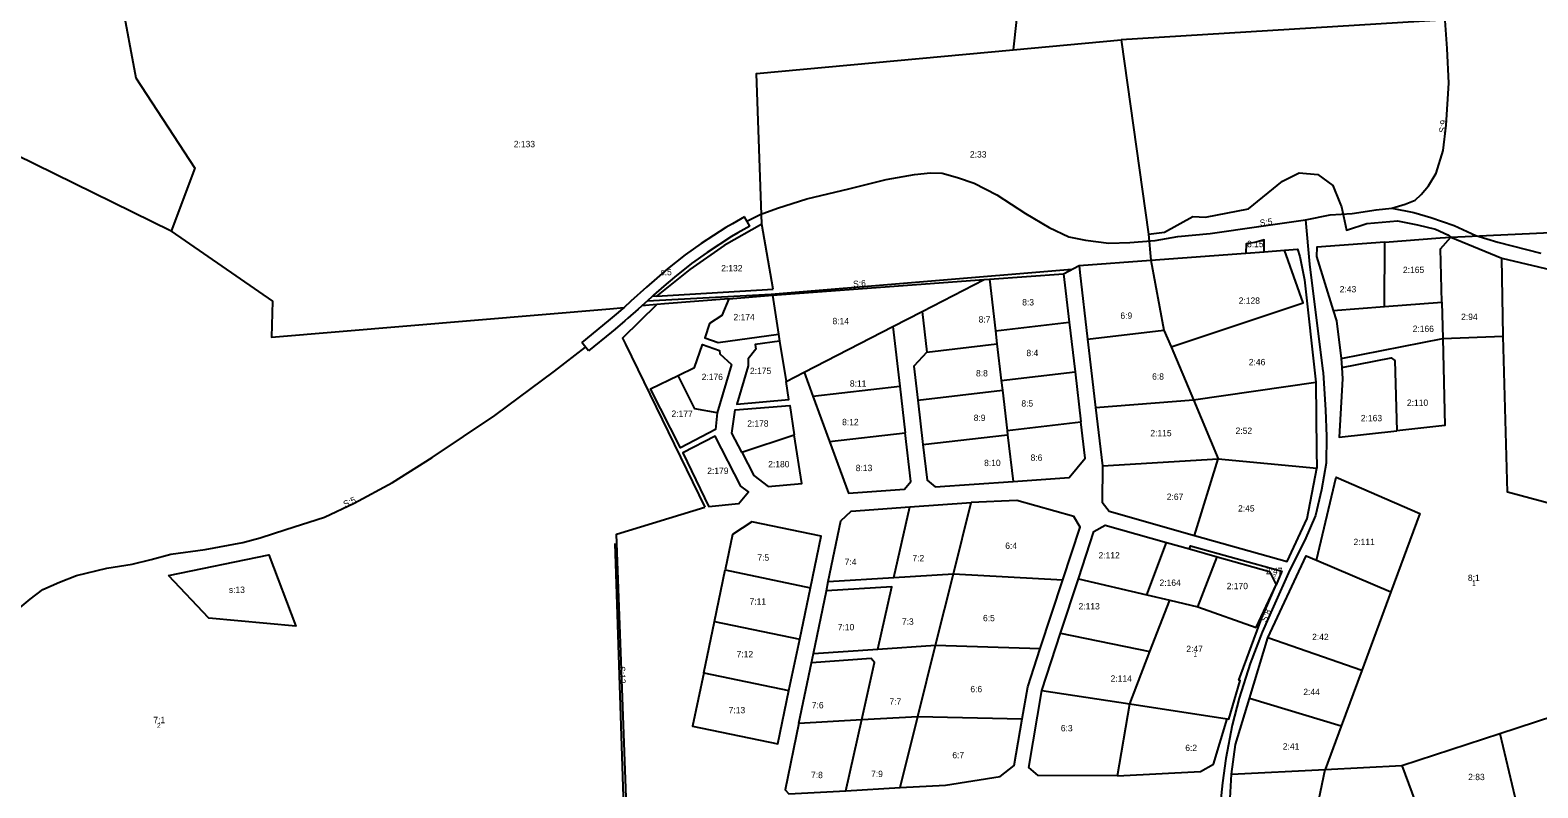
# Model space of a CAD drawing. Extents: x 140824 to 143748, y 6547319 to 6550906.
# Drawn here: x 141835 to 142666, y 6548333 to 6548751 of the extents above; entities that cross this region are included whole.
import ezdxf

# ---------------------------------------------------------------- set-up
doc = ezdxf.new("R2010")
doc.units = 0
for name, color, linetype in [('FAST Fastighetsgräns', 7, 'Continuous'), ('FAST Mittlinjeredovisad samfällighet', 7, 'Continuous'), ('FAST Områdesnummer för fastighet', 7, 'Continuous'), ('FAST Registernummer för fastighet', 7, 'Continuous'), ('FAST Registernummer för mittlinjeredovisad samfällighet', 7, 'Continuous'), ('FAST Registernummer för samfällighet', 7, 'Continuous'), ('FAST Traktgräns', 7, 'Continuous'), ('FAST Tätningsgräns för fastighetsgräns', 7, 'Continuous')]:
    doc.layers.add(name, color=color, linetype=linetype)

msp = doc.modelspace()

# ---------------------------------------------------------------- linework, layer by layer
at = {"layer": 'FAST Fastighetsgräns'}
for p, q in [((142612.62, 6548756.38), (142436.27, 6548745.52)), ((142376.67, 6548740.04), (142436.27, 6548745.52)), ((142436.27, 6548745.52), (142451.32, 6548638.42)), ((142244.43, 6548608.1), (142238.13, 6548643.9)), ((142618.17, 6548636.75), (142712.61, 6548641.27)), ((142451.32, 6548638.42), (142452.72, 6548624.05)), ((142581.59, 6548598.48), (142581.71, 6548634)), ((142618.17, 6548636.75), (142646.14, 6548625.16)), ((142413.09, 6548621.11), (142452.72, 6548624.05)), ((142452.72, 6548624.05), (142505.12, 6548627.98)), ((142452.72, 6548624.05), (142459.92, 6548585.38)), ((142505.12, 6548627.98), (142515.12, 6548628.72)), ((142515.12, 6548628.72), (142526.39, 6548629.56)), ((142646.9, 6548582.14), (142646.14, 6548625.16)), ((142363.66, 6548613.55), (142404.56, 6548616.56)), ((142404.56, 6548616.56), (142413.09, 6548621.11)), ((142404.56, 6548616.56), (142407.67, 6548589.89)), ((142180.02, 6548604.12), (142244.43, 6548608.1)), ((142244.03, 6548604.8), (142360.68, 6548613.33)), ((142326.5, 6548595.7), (142360.68, 6548613.33)), ((142360.68, 6548613.33), (142363.66, 6548613.55)), ((142363.66, 6548613.55), (142366.98, 6548585.13)), ((142180.18, 6548599.54), (142171.97, 6548598.82)), ((142180.02, 6548604.12), (142177.73, 6548604)), ((142220.04, 6548602.8), (142244.03, 6548604.8)), ((142244.03, 6548604.8), (142247.33, 6548583.3)), ((142553.22, 6548596.34), (142581.59, 6548598.48)), ((142581.59, 6548598.48), (142613.1, 6548600.85)), ((142613.1, 6548600.85), (142613.61, 6548580.87)), ((142310.4, 6548587.39), (142326.5, 6548595.7)), ((142326.5, 6548595.7), (142329.11, 6548573.37)), ((142247.33, 6548583.3), (142247.93, 6548579.37)), ((142261.52, 6548562.17), (142310.4, 6548587.39)), ((142310.4, 6548587.39), (142314.22, 6548554.61)), ((142366.98, 6548585.13), (142407.67, 6548589.89)), ((142366.98, 6548585.13), (142367.83, 6548577.88)), ((142407.67, 6548589.89), (142410.88, 6548562.36)), ((142417.82, 6548580.53), (142459.92, 6548585.38)), ((142459.92, 6548585.38), (142463.81, 6548576.19)), ((142613.61, 6548580.87), (142646.9, 6548582.14)), ((142247.93, 6548579.37), (142251.5, 6548557.04)), ((142329.11, 6548573.37), (142367.83, 6548577.88)), ((142367.83, 6548577.88), (142370.18, 6548557.62)), ((142417.82, 6548580.53), (142422.23, 6548542.71)), ((142463.81, 6548576.19), (142476.12, 6548547.08)), ((142557.57, 6548569.86), (142613.61, 6548580.87)), ((142557.57, 6548569.86), (142557.98, 6548564.85)), ((142251.5, 6548557.04), (142261.52, 6548562.17)), ((142261.52, 6548562.17), (142266.33, 6548549.02)), ((142370.18, 6548557.62), (142410.88, 6548562.36)), ((142370.18, 6548557.62), (142370.8, 6548552.29)), ((142410.88, 6548562.36), (142414.09, 6548534.85)), ((142266.33, 6548549.02), (142314.22, 6548554.61)), ((142266.33, 6548549.02), (142275.51, 6548523.93)), ((142314.22, 6548554.61), (142317.23, 6548528.78)), ((142324.14, 6548546.85), (142370.8, 6548552.29)), ((142370.8, 6548552.29), (142373.39, 6548530.11)), ((142476.12, 6548547.08), (142543.64, 6548556.8)), ((142324.14, 6548546.85), (142327.02, 6548522.28)), ((142422.23, 6548542.71), (142476.12, 6548547.08)), ((142422.23, 6548542.71), (142425.97, 6548510.6)), ((142476.12, 6548547.08), (142489.77, 6548514.39)), ((142373.39, 6548530.11), (142414.09, 6548534.85)), ((142227.15, 6548518.07), (142255.97, 6548527.63)), ((142275.51, 6548523.93), (142317.23, 6548528.78)), ((142327.02, 6548522.28), (142373.67, 6548527.71)), ((142373.39, 6548530.11), (142373.67, 6548527.71)), ((142373.67, 6548527.71), (142376.67, 6548501.95)), ((142425.97, 6548510.6), (142489.77, 6548514.39)), ((142476.77, 6548472.17), (142489.77, 6548514.39)), ((142489.77, 6548514.39), (142544.15, 6548509.25)), ((142225.38, 6548489.62), (142208.89, 6548487.99)), ((142311.01, 6548448.95), (142319.78, 6548487.89)), ((142319.78, 6548487.89), (142353.6, 6548490.29)), ((142343.81, 6548450.98), (142353.6, 6548490.29)), ((142450.39, 6548439.46), (142461.38, 6548468.26)), ((142461.38, 6548468.26), (142473.92, 6548464.73)), ((142473.92, 6548464.73), (142489.32, 6548460.39)), ((142478.62, 6548432.83), (142489.32, 6548460.39)), ((142489.32, 6548460.39), (142518.11, 6548452.24)), ((142544.04, 6548458.54), (142584.97, 6548441.06)), ((142212.02, 6548424.75), (142217.92, 6548453.14)), ((142217.92, 6548453.14), (142264.93, 6548443.36)), ((142274.83, 6548446.71), (142311.01, 6548448.95)), ((142311.01, 6548448.95), (142343.81, 6548450.98)), ((142334.01, 6548411.69), (142343.81, 6548450.98)), ((142343.81, 6548450.98), (142404.1, 6548447.75)), ((142518.11, 6548452.24), (142521.83, 6548444.93)), ((142259.03, 6548414.99), (142264.93, 6548443.36)), ((142266.61, 6548407.06), (142273.78, 6548441.64)), ((142273.78, 6548441.64), (142274.83, 6548446.71)), ((142391.68, 6548409.74), (142404.1, 6548447.75)), ((142402.89, 6548418.18), (142412.76, 6548448.29)), ((142412.76, 6548448.29), (142450.39, 6548439.46)), ((142510.67, 6548421.37), (142521.83, 6548444.93)), ((142584.97, 6548441.06), (142568.92, 6548397.7)), ((142450.39, 6548439.46), (142463.05, 6548436.49)), ((142452.16, 6548408.2), (142463.05, 6548436.49)), ((142463.05, 6548436.49), (142478.62, 6548432.83)), ((142478.62, 6548432.83), (142510.67, 6548421.37)), ((142206.11, 6548396.36), (142212.02, 6548424.75)), ((142212.02, 6548424.75), (142259.03, 6548414.99)), ((142392.57, 6548386.71), (142402.89, 6548418.18)), ((142402.89, 6548418.18), (142452.16, 6548408.2)), ((142507.05, 6548382.29), (142517.12, 6548415.77)), ((142568.92, 6548397.7), (142517.12, 6548415.77)), ((142253.13, 6548386.61), (142259.03, 6548414.99)), ((142266.61, 6548407.06), (142302.1, 6548409.5)), ((142302.1, 6548409.5), (142334.01, 6548411.69)), ((142324.19, 6548372.34), (142334.01, 6548411.69)), ((142334.01, 6548411.69), (142391.68, 6548409.74)), ((142441.09, 6548379.26), (142452.16, 6548408.2)), ((142258.62, 6548368.66), (142265.55, 6548401.97)), ((142265.55, 6548401.97), (142266.61, 6548407.06)), ((142206.11, 6548396.36), (142253.13, 6548386.61)), ((142568.92, 6548397.7), (142557.56, 6548367.02)), ((142392.57, 6548386.71), (142441.09, 6548379.26)), ((142434.25, 6548339.55), (142441.09, 6548379.26)), ((142441.09, 6548379.26), (142494.79, 6548371.02)), ((142557.56, 6548367.02), (142507.05, 6548382.29)), ((142645.15, 6548362.91), (142685.57, 6548376.24)), ((142258.62, 6548368.66), (142293.29, 6548370.64)), ((142284.43, 6548331.36), (142293.29, 6548370.64)), ((142293.29, 6548370.64), (142324.19, 6548372.34)), ((142314.4, 6548333.04), (142324.19, 6548372.34)), ((142324.19, 6548372.34), (142381.74, 6548370.99)), ((142557.56, 6548367.02), (142548.71, 6548343.09)), ((142591.08, 6548345.34), (142645.15, 6548362.91)), ((142645.15, 6548362.91), (142659.85, 6548300.41)), ((142497.13, 6548340.5), (142548.71, 6548343.09)), ((142539.85, 6548300.23), (142548.71, 6548343.09)), ((142548.71, 6548343.09), (142591.08, 6548345.34)), ((142591.08, 6548345.34), (142600.25, 6548320.44)), ((142284.43, 6548331.36), (142314.4, 6548333.04)), ((142494.77, 6548296.57), (142497.13, 6548340.5))]:
    msp.add_line(p, q, dxfattribs=at)
for points in [[(142406.77, 6549013.95), (142404.62, 6548994.39), (142376.67, 6548740.04)], [(142238.13, 6548643.9), (142235.26, 6548727.03), (142376.67, 6548740.04)], [(142451.32, 6548638.42), (142460.23, 6548639.48), (142475.91, 6548648.18), (142482.77, 6548647.83), (142506.54, 6548652.43), (142525.2, 6548667.6), (142534.41, 6548672.19), (142544.66, 6548671.32), (142552.94, 6548665.22), (142556.84, 6548655.7), (142557.78, 6548653.39), (142560.57, 6548640.61), (142571.68, 6548644.29), (142588.72, 6548645.8), (142599.66, 6548643.49), (142609.59, 6548641.21), (142616.5, 6548638.01), (142618.17, 6548636.75)], [(141912.47, 6548640.08), (141968.36, 6548601.48), (141967.78, 6548581.5), (142154.26, 6548597.18), (142162.17, 6548597.96)], [(142228.54, 6548647.93), (142222.02, 6548644.18), (142218.37, 6548642.08), (142204.68, 6548633.21), (142195.85, 6548626.92), (142186.22, 6548619.24), (142180.2, 6548614.14), (142174.55, 6548609.08), (142166, 6548601.39), (142162.17, 6548597.96)], [(142231.48, 6548642.82), (142224.97, 6548639.07), (142221.45, 6548637.04), (142207.99, 6548628.33), (142199.41, 6548622.21), (142189.97, 6548614.68), (142184.07, 6548609.7), (142178.5, 6548604.7), (142177.73, 6548604)], [(142238.13, 6548643.9), (142217.48, 6548632.15), (142198.42, 6548618.92), (142180.02, 6548604.12)], [(142515.12, 6548628.72), (142515.22, 6548635.22), (142510.09, 6548633.87), (142505.3, 6548633.08), (142505.12, 6548627.98)], [(142581.71, 6548634), (142544.11, 6548631.16), (142543.97, 6548626.07), (142553.22, 6548596.34)], [(142581.71, 6548634), (142612.18, 6548636.29), (142618.17, 6548636.75)], [(142613.1, 6548600.85), (142612.34, 6548630.31), (142618.17, 6548636.75)], [(142463.81, 6548576.19), (142536.57, 6548600.5), (142526.39, 6548629.56)], [(142526.39, 6548629.56), (142533.58, 6548630.1), (142534.73, 6548626.14), (142537.36, 6548613.25), (142543.64, 6548556.8)], [(142646.14, 6548625.16), (142703.75, 6548611.52), (142717.51, 6548603.13), (142727.33, 6548596.85), (142728.81, 6548474.79), (142649.42, 6548496.06), (142646.9, 6548582.14)], [(142413.09, 6548621.11), (142413.55, 6548617.23), (142417.82, 6548580.53)], [(142171.97, 6548598.82), (142171.73, 6548598.6), (142169.94, 6548596.99), (142164.33, 6548591.97), (142162.68, 6548590.61), (142157.3, 6548585.97), (142155.21, 6548584.26), (142142.67, 6548574.01)], [(142180.18, 6548599.54), (142161.39, 6548581.06), (142163.06, 6548577.64), (142206.82, 6548487.8)], [(142177.73, 6548604), (142175.05, 6548601.59), (142172.04, 6548598.88), (142171.97, 6548598.82)], [(142220.04, 6548602.8), (142184.47, 6548599.89), (142180.18, 6548599.54)], [(142220.04, 6548602.8), (142216.13, 6548593.45), (142209.26, 6548589.05), (142206.65, 6548581.23), (142214.14, 6548578.68), (142247.33, 6548583.3)], [(142162.17, 6548597.96), (142160.48, 6548596.44), (142158.87, 6548595.11), (142153.51, 6548590.49), (142138.94, 6548578.58)], [(142553.22, 6548596.34), (142555.03, 6548590.53), (142557.57, 6548569.86)], [(142191.95, 6548560.39), (142201.07, 6548564.81), (142205.36, 6548577.45), (142214.79, 6548574.27), (142215.05, 6548572.31), (142221.52, 6548566.52), (142213.52, 6548539.9)], [(142247.93, 6548579.37), (142234.51, 6548577.48), (142234.87, 6548574.93), (142230.63, 6548569.64), (142230.71, 6548565.71), (142224.35, 6548544.64), (142253.1, 6548547.1), (142251.5, 6548557.04)], [(142613.61, 6548580.87), (142614.75, 6548532.86), (142588.24, 6548529.96)], [(142329.11, 6548573.37), (142322.01, 6548565.52), (142324.14, 6548546.85)], [(142557.98, 6548564.85), (142585.25, 6548570.24), (142587.26, 6548568.63), (142588.24, 6548529.96)], [(142213.52, 6548539.9), (142212.68, 6548530.61), (142193.24, 6548520.49), (142176.76, 6548553.08), (142191.95, 6548560.39)], [(142213.52, 6548539.9), (142201.28, 6548542.01), (142191.95, 6548560.39)], [(142557.98, 6548564.85), (142558.4, 6548558.61), (142556.43, 6548526.48), (142588.24, 6548529.96)], [(142543.64, 6548556.8), (142544.07, 6548519.07), (142544.15, 6548509.25)], [(142227.15, 6548518.07), (142221.6, 6548528.69), (142223.44, 6548541.51), (142253.57, 6548543.93), (142255.97, 6548527.63)], [(142376.67, 6548501.95), (142407.59, 6548504.14), (142416.42, 6548514.78), (142414.09, 6548534.85)], [(142225.38, 6548489.62), (142230.81, 6548496.21), (142226.62, 6548499.3), (142212.4, 6548527.01), (142194.66, 6548517.79), (142208.89, 6548487.99)], [(142227.15, 6548518.07), (142233.81, 6548505.27), (142241.61, 6548499.26), (142260.3, 6548500.84), (142255.97, 6548527.63)], [(142275.51, 6548523.93), (142285.91, 6548495.51), (142316.83, 6548497.71), (142320.35, 6548501.96), (142317.23, 6548528.78)], [(142327.02, 6548522.28), (142329.33, 6548502.6), (142333.78, 6548498.91), (142376.67, 6548501.95)], [(142425.97, 6548510.6), (142425.84, 6548490.61), (142429.65, 6548485.49), (142476.77, 6548472.17)], [(142476.77, 6548472.17), (142527.78, 6548457.76), (142538.9, 6548481.58), (142544.15, 6548509.25)], [(142544.04, 6548458.54), (142554.87, 6548504.24), (142600.91, 6548484.22), (142584.97, 6548441.06)], [(142404.1, 6548447.75), (142413.69, 6548476.72), (142410.13, 6548482.63), (142378.7, 6548491.45), (142353.6, 6548490.29)], [(142163.49, 6548322.6), (142158.09, 6548472.86), (142206.82, 6548487.8)], [(142274.83, 6548446.71), (142281.8, 6548480.29), (142287.43, 6548485.6), (142319.78, 6548487.89)], [(142264.93, 6548443.36), (142270.83, 6548471.74), (142232.64, 6548479.68), (142222, 6548472.69), (142217.92, 6548453.14)], [(142412.76, 6548448.29), (142421.3, 6548474.34), (142427.49, 6548477.8), (142461.38, 6548468.26)], [(142473.92, 6548464.73), (142474.6, 6548466.51), (142524.92, 6548452.46), (142521.83, 6548444.93)], [(141910.98, 6548450.1), (141966.32, 6548461.52), (141981.18, 6548422.1), (141933.3, 6548426.46), (141910.98, 6548450.1)], [(142517.12, 6548415.77), (142538.38, 6548460.96), (142544.04, 6548458.54)], [(142302.1, 6548409.5), (142309.86, 6548443.86), (142273.78, 6548441.64)], [(142494.79, 6548371.02), (142495.68, 6548370.88), (142501.93, 6548392.18), (142501.19, 6548392.3), (142513.89, 6548426.73), (142521.83, 6548444.93)], [(142381.74, 6548370.99), (142384.8, 6548388.66), (142391.68, 6548409.74)], [(142293.29, 6548370.64), (142300.34, 6548402), (142298.4, 6548404.26), (142265.55, 6548401.97)], [(142206.11, 6548396.36), (142200, 6548367), (142247.03, 6548357.25), (142253.13, 6548386.61)], [(142434.25, 6548339.55), (142390.57, 6548339.72), (142385.31, 6548344.23), (142392.57, 6548386.71)], [(142497.13, 6548340.5), (142499.4, 6548356.85), (142507.05, 6548382.29)], [(142258.62, 6548368.66), (142250.96, 6548331.92), (142252.99, 6548329.6), (142284.43, 6548331.36)], [(142314.4, 6548333.04), (142339.44, 6548334.48), (142369.55, 6548339.12), (142377.29, 6548345.17), (142381.74, 6548370.99)], [(142434.25, 6548339.55), (142480.1, 6548341.97), (142487.26, 6548346.02), (142494.79, 6548371.02)]]:
    msp.add_lwpolyline(points, dxfattribs=at)
at = {"layer": 'FAST Mittlinjeredovisad samfällighet'}
msp.add_line((142157.05, 6548467.7), (142161.8, 6548322.48), dxfattribs=at)
for points in [[(142585.58, 6548652.76), (142592.83, 6548654.89), (142598.47, 6548657.22), (142601.64, 6548660.21), (142605.74, 6548665.08), (142610.04, 6548671.99), (142613.92, 6548684.49), (142615.5, 6548698.53), (142616.91, 6548721.66), (142615.99, 6548740.75), (142614.88, 6548756.3), (142614.86, 6548756.52)], [(142229.97, 6548645.59), (142237.3, 6548649.2), (142246.79, 6548652.74), (142262.93, 6548657.84), (142286.12, 6548663.48), (142306.8, 6548668.6), (142322.42, 6548671.37), (142331.25, 6548672.14), (142337.69, 6548671.96), (142345.99, 6548669.67), (142355.28, 6548666.46), (142367.71, 6548660.09), (142383.55, 6548649.81), (142396.67, 6548642.09), (142407.52, 6548636.94), (142416.71, 6548635.06), (142429.56, 6548633.37), (142441.01, 6548633.77), (142454.98, 6548634.98), (142467.51, 6548637.11), (142485.45, 6548638.79), (142512.25, 6548642.71), (142537.88, 6548646.22), (142551.6, 6548649.05), (142563.65, 6548649.87), (142576.9, 6548651.84), (142585.58, 6548652.76), (142597.69, 6548650.35), (142606.99, 6548647.59), (142619.92, 6548643.26), (142631.93, 6548637.63), (142644, 6548633.91), (142667.73, 6548627.94)], [(142537.88, 6548646.22), (142540.11, 6548621.81), (142547.32, 6548564.28), (142547.62, 6548561.9), (142548.94, 6548541.48), (142549.54, 6548526.8), (142549.27, 6548512.14), (142546.78, 6548497.25), (142543.45, 6548483.27), (142537.63, 6548469.51), (142529.38, 6548453.18), (142520.29, 6548432.91), (142514.02, 6548418.86), (142507.36, 6548401.6), (142501.38, 6548382.42), (142497.58, 6548367.57), (142493.97, 6548349.05), (142492.27, 6548335.76), (142489.65, 6548311.19)], [(142175.02, 6548601.57), (142243.22, 6548605.36), (142409.18, 6548619.06)], [(141827.07, 6548430.66), (141834.73, 6548437.04), (141841.63, 6548442.41), (141850.84, 6548446.4), (141860.34, 6548450.08), (141877.03, 6548454.15), (141891.03, 6548456.38), (141901.36, 6548458.87), (141912.3, 6548461.78), (141931.15, 6548464.46), (141951.94, 6548468.26), (141961.55, 6548470.91), (141975.76, 6548475.49), (141996.93, 6548482.35), (142013.43, 6548489.94), (142034.59, 6548501.36), (142056.41, 6548515.25), (142090.95, 6548538.3), (142123.78, 6548562.72), (142140.93, 6548576.12)]]:
    msp.add_lwpolyline(points, dxfattribs=at)
at = {"layer": 'FAST Traktgräns'}
msp.add_line((141912.47, 6548640.08), (141826.77, 6548682.21), dxfattribs=at)
msp.add_lwpolyline([(141972.63, 6548844.89), (141874.33, 6548830.86), (141877.61, 6548818.09), (141882.35, 6548808.96), (141885.06, 6548798.88), (141889.56, 6548781.75), (141885.13, 6548766.87), (141892.91, 6548724.65), (141925.47, 6548674.71), (141912.47, 6548640.08)], dxfattribs=at)
at = {"layer": 'FAST Tätningsgräns för fastighetsgräns'}
for p, q in [((142231.48, 6548642.82), (142228.54, 6548647.93)), ((142142.67, 6548574.01), (142138.94, 6548578.58))]:
    msp.add_line(p, q, dxfattribs=at)

# ---------------------------------------------------------------- texts
at = {"layer": 'FAST Områdesnummer för fastighet'}
for s, p in [('2', (142519.88, 6548448.31)), ('1', (142629.8, 6548444.55)), ('1', (142476.24, 6548405.36)), ('2', (141904.71, 6548366.11))]:
    msp.add_text(s, height=2.5, dxfattribs=at).set_placement(p)
at = {"layer": 'FAST Registernummer för fastighet'}
for s, p in [('2:133', (142101.39, 6548686.36)), ('2:33', (142352.91, 6548680.66)), ('8:15', (142505.74, 6548631.21)), ('2:132', (142215.78, 6548617.91)), ('2:165', (142591.69, 6548616.99)), ('2:43', (142556.82, 6548606.28)), ('8:3', (142381.73, 6548599.06)), ('2:128', (142501.11, 6548599.96)), ('2:174', (142222.53, 6548590.9)), ('8:14', (142277.13, 6548588.72)), ('8:7', (142357.71, 6548589.62)), ('6:9', (142435.88, 6548591.7)), ('2:94', (142623.74, 6548591.07)), ('2:166', (142597.05, 6548584.46)), ('8:4', (142384.07, 6548571.09)), ('2:46', (142506.68, 6548566.08)), ('2:176', (142205, 6548557.89)), ('2:175', (142231.62, 6548561.24)), ('8:11', (142286.71, 6548554.26)), ('8:8', (142356.26, 6548559.91)), ('6:8', (142453.37, 6548558.12)), ('2:177', (142188.36, 6548537.59)), ('8:5', (142381.28, 6548543.28)), ('2:110', (142593.86, 6548543.65)), ('2:178', (142230.15, 6548532.18)), ('8:12', (142282.44, 6548533)), ('8:9', (142354.99, 6548535.31)), ('2:163', (142568.46, 6548535.18)), ('2:115', (142452.41, 6548526.91)), ('2:52', (142499.41, 6548528.2)), ('8:6', (142386.35, 6548513.36)), ('2:179', (142208.07, 6548506.12)), ('2:180', (142241.68, 6548509.79)), ('8:13', (142289.96, 6548507.65)), ('8:10', (142360.73, 6548510.44)), ('2:67', (142461.46, 6548491.79)), ('2:45', (142500.76, 6548485.38)), ('6:4', (142372.4, 6548464.75)), ('2:111', (142564.43, 6548466.83)), ('7:5', (142235.71, 6548458.21)), ('7:4', (142283.82, 6548455.79)), ('7:2', (142321.19, 6548457.91)), ('2:112', (142423.81, 6548459.46)), ('2:47', (142516.12, 6548450.81)), ('8:1', (142627.5, 6548447.05)), ('2:164', (142457.46, 6548444.35)), ('2:170', (142494.5, 6548442.53)), ('7:11', (142231.4, 6548434.02)), ('2:113', (142412.8, 6548431.36)), ('7:3', (142315.41, 6548422.92)), ('6:5', (142360.12, 6548424.86)), ('7:10', (142280.03, 6548419.85)), ('2:42', (142541.59, 6548414.44)), ('7:12', (142224.26, 6548404.93)), ('2:47', (142472.24, 6548407.86)), ('2:114', (142430.48, 6548391.47)), ('6:6', (142353.15, 6548385.68)), ('2:44', (142536.75, 6548384.1)), ('7:13', (142219.87, 6548374.07)), ('7:6', (142265.72, 6548376.8)), ('7:7', (142308.51, 6548378.74)), ('7:1', (141902.64, 6548368.61)), ('6:3', (142403.05, 6548364.1)), ('2:41', (142525.45, 6548354.07)), ('6:7', (142343.2, 6548349.22)), ('6:2', (142471.66, 6548353.27)), ('7:8', (142265.29, 6548338.28)), ('7:9', (142298.4, 6548338.86)), ('2:83', (142627.65, 6548337.18))]:
    msp.add_text(s, height=3.5, dxfattribs=at).set_placement(p)
at = {"layer": 'FAST Registernummer för mittlinjeredovisad samfällighet'}
for s, rotation, p in [('S:9', 83.652, (142615.02, 6548694.18)), ('S:5', 7.631, (142512.95, 6548642.81)), ('S:6', 4.584, (142288.62, 6548609.12)), ('S:5', 24.82, (142008.35, 6548487.6)), ('S:8', 65.708, (142516.33, 6548424.08)), ('S:12', 271.947, (142159.26, 6548399.98))]:
    msp.add_text(s, height=3.5, rotation=rotation, dxfattribs=at).set_placement(p)
at = {"layer": 'FAST Registernummer för samfällighet'}
for s, p in [('s:5', (142182.24, 6548615.73)), ('s:13', (141944.27, 6548440.48))]:
    msp.add_text(s, height=3.5, dxfattribs=at).set_placement(p)

doc.saveas('drawing.dxf')
